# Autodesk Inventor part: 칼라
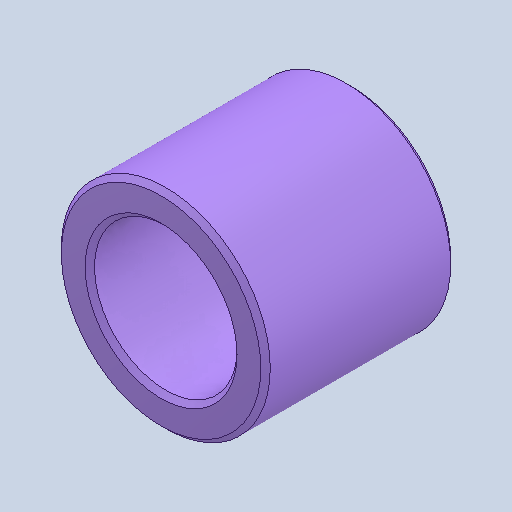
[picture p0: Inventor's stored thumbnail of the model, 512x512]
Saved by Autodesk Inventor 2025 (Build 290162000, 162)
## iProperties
Created: 2025-08
Part Number: 칼라
Material: 스테인리스강
Document SubType Name: Modeling
Designer: infra02
Density: 8.08 g/cm^3
Appearance: 기본값
Author: jhkim
Sending System: Autodesk Inventor 2026
Preprocessor: ST-DEVELOPER v20.1
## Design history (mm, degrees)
feature "솔리드1"
node "솔리드2"
